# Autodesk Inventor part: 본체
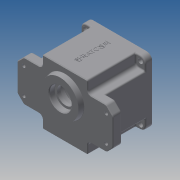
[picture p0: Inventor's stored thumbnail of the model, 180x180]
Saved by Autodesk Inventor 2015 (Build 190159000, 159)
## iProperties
Created: 2016-02
Part Number: 본체
Material: Generic
Document SubType Name: Modeling
Designer: Administrator
Density: 1 g/cm^3
Appearance: Default
Author: Administrator
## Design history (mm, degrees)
sketch "Sketch1"
  geometry: L1 (-70, -20)-(-70, 20); L2 (-33, 47)-(33, 47); L3 (70, 20)-(70, -20); L4 (70, -47)-(-70, 47); L5 (-70, -47)-(70, 47); L6 (60, 30)-(33, 30); L7 (33, 30)-(33, 47); L8 (0, 0)-(114.334, 0); L9 (0, 0)-(0, 123.01); L10 (-33, 30)-(-33, 47); L11 (-60, 30)-(-33, 30); L12 (60, -30)-(33, -30); L13 (33, -30)-(33, -47); L14 (0, 0)-(0, -123.01); L15 (-33, -47)-(33, -47); L16 (-33, -30)-(-33, -47); L17 (-60, -30)-(-33, -30); L18 (70, 20)-(60, 30); L19 (-60, 30)-(-70, 20); L20 (-70, -20)-(-60, -30); L21 (60, -30)-(70, -20); 4 further points
  constraints: 42 end point, 10 symmetric about line, 8 point on line, 2 horizontal, 2 midpoint, 1 parallel, 1 perpendicular, 1 vertical
  dimensions: "d0" = 140 distance of L4.end L5.end; "d1" = 94 distance of L5.start L4.end; "d2" = 66 distance from line of L10 L2.end; "d3" = 60 distance of point (-70, -30) point (-70, 30); "d4" = 94 distance between parallel lines of L15 L2; "d5" = 140 distance between parallel lines of L1 L3; "d6" = 10 distance of L3.start point (70, 30); "d7" = 10 distance of L6.start point (70, 30) (= d6); "d8" = 10 distance of L11.start point (-70, 30); "d9" = 10 distance of L1.end point (-70, 30) (= d8); "d10" = 10 distance of L1.start point (-70, -30) (= d8); "d11" = 10 distance of L17.start point (-70, -30) (= d10); "d12" = 10 distance of L12.start point (70, -30) (= d8); "d13" = 10 distance of L3.end point (70, -30) (= d12)
extrude "Extrusion1" new body sketch "Sketch1" distance "d14" = 13; taper "d15" = 0 deg
sketch "Sketch4"
  geometry: L1 (60, -19)-(-60, -19); L2 (-60, -19)-(-60, 19); L3 (-60, 19)-(60, 19); L4 (60, 19)-(60, -19); L5 (60, -19)-(-60, 19); L6 (-60, -19)-(60, 19); 5 further points
  constraints: 12 end point, 4 coincident, 2 midpoint, 2 parallel, 1 horizontal, 1 perpendicular
  dimensions: "d16" = 120 distance of L2.end L3.end; "d17" = 38 distance of L1.end L2.end
hole "Hole1" sketch "Sketch4" at (-60, 19), (-60, -19), (60, -19), (60, 19) diameter "d18" = 5; stored, may be unused: countersink angle "d22" = 90 deg, drill point angle "d24" = 118 deg; dims "d19" = 6, "d20" = 9, "d21" = 4, "d23" = 8
fillet "Fillet1" dims "d25" = 5
sketch "Sketch5"
  geometry: L1 (-33, -47)-(33, -47) reference; L2 (33, 47)-(-33, 47) reference; L3 (33, 35)-(33, 47) reference; L4 (-33, 47)-(-33, 35) reference; L5 (-33, -35)-(-33, -47) reference; L6 (33, -47)-(33, -35) reference; L7 (47, -30)-(47, 30); L8 (-47, -30)-(-47, 30); L9 (-60, -30)-(-38, -30) reference; L10 (38, -30)-(60, -30) reference; L11 (60, 30)-(38, 30) reference; L12 (-38, 30)-(-60, 30) reference; A1 r 5 centre (38, 35) between (33, 35) and (38, 30) reference; A2 r 5 centre (-38, 35) between (-38, 30) and (-33, 35) reference; A3 r 5 centre (-38, -35) between (-33, -35) and (-38, -30) reference; A4 r 5 centre (38, -35) between (38, -30) and (33, -35) reference; 1 further point
  constraints: 4 end point, 4 point on line, 2 vertical
  dimensions: "d26" = 47 distance from line of point (0, 0) L7; "d27" = 94 distance between parallel lines of L8 L7
extrude "Extrusion2" join sketch "Sketch5" distance "d28" = 57; taper "d29" = 0 deg
sketch "Sketch6"
  geometry: L1 (33, -47)-(-33, -47) reference; L2 (47, 30)-(47, -30) reference; L3 (-47, -30)-(-47, 30) reference; L4 (-33, 47)-(33, 47) reference; L5 (47, -30)-(47, -39); L6 (33, -47)-(39, -47); L7 (-33, -47)-(-39, -47); L8 (-47, -30)-(-47, -39); L9 (47, 30)-(47, 39); L10 (33, 47)-(39, 47); L11 (-33, 47)-(-39, 47); L12 (-47, 30)-(-47, 39); A1 r 8 centre (39, -39) between (39, -47) and (47, -39); A2 r 8 centre (-39, -39) between (-47, -39) and (-39, -47); A3 r 8 centre (-39, 39) between (-39, 47) and (-47, 39); A4 r 8 centre (39, 39) between (47, 39) and (39, 47); 1 further point
  constraints: 16 end point, 8 point on circle, 8 tangent, 4 centre point, 4 vertical, 3 equal radius, 3 horizontal, 1 perpendicular
  dimensions: "d30" = 8 radius of A1
extrude "Extrusion3" join sketch "Sketch6" distance "d31" = 10; taper "d32" = 0 deg
sketch "Sketch7"
  geometry: L1 (40, 40)-(-40, 40); L2 (-40, 40)-(-40, -40); L3 (-40, -40)-(40, -40); L4 (40, -40)-(40, 40); L5 (40, 40)-(-40, -40); L6 (-40, 40)-(40, -40); 5 further points
  constraints: 12 end point, 4 coincident, 2 midpoint, 2 parallel, 1 horizontal, 1 perpendicular
  dimensions: "d33" = 80 distance of L3.end L2.end; "d34" = 80 distance of L2.end L1.end
hole "Hole2" sketch "Sketch7" at (40, -40), (-40, -40), (-40, 40), (40, 40) diameter "d35" = 7; stored, may be unused: countersink angle "d39" = 90 deg, drill point angle "d41" = 118 deg; dims "d36" = 6, "d37" = 9, "d38" = 4, "d40" = 8
sketch "Sketch8"
  geometry: C1 r 43 at (0, 0); 1 further point
  constraints: 1 centre point, 1 coincident
  dimensions: "d42" = 86 diameter of C1
extrude "Extrusion4" cut sketch "Sketch8" distance "d43" = 9; taper "d44" = 0 deg
sketch "Sketch9"
  geometry: L1 (-39, -47)-(39, -47) reference; L2 (47, -39)-(47, 39) reference; L3 (39, 47)-(-39, 47) reference; L4 (-47, 39)-(-47, -39) reference; L5 (-35.777, -4)-(-39.799, -4); L6 (-35.777, 4)-(-39.799, 4); L7 (-42.814, 4)-(-54.27, 4); L8 (39.799, 4)-(35.777, 4); L9 (39.799, -4)-(35.777, -4); C1 r 3.5 at (-40, 40) reference; C2 r 3.5 at (40, -40) reference; C3 r 3.5 at (-40, -40) reference; C4 r 3.5 at (40, 40) reference; A1 r 8 centre (39, -39) between (39, -47) and (47, -39) reference; A2 r 8 centre (39, 39) between (47, 39) and (39, 47) reference; A3 r 8 centre (-39, 39) between (-39, 47) and (-47, 39) reference; A4 r 8 centre (-39, -39) between (-47, -39) and (-39, -47) reference; A5 r 36 centre (0, 0) between (36, 0) and (-36, 0); A6 r 4 centre (36, 0) between (36, 4) and (36, -4); A7 r 4 centre (-36, 0) between (-36, -4) and (-36, 4); A8 r 40 centre (0, 0) between (-39.799, -4) and (39.799, -4); A9 r 40 centre (0, 0) between (39.799, 4) and (-39.799, 4); 2 further points
  constraints: 14 point on circle, 10 end point, 5 centre point, 5 tangent, 4 coincident, 4 point on line, 3 perpendicular, 2 horizontal, 2 horizontal alignment, 1 equal radius, 2 other
  dimensions: "d45" = 36 radius of A5; "d46" = 4 radius of A6; "d49" = 40 radius of A8; "d50" = 40 radius of A9
extrude "Extrusion5" cut sketch "Sketch9" distance "d51" = 62; taper "d52" = 0 deg
sketch "Sketch10"
  geometry: A1 r 21 centre (0, -11) between (-12.163, 6.119) and (12.163, 6.119); A2 r 15 centre (0, 20) between (11.584, 10.47) and (-11.584, 10.47); A3 r 3 centre (13.901, 8.565) between (11.584, 10.47) and (12.163, 6.119); A4 r 3 centre (-13.901, 8.565) between (-12.163, 6.119) and (-11.584, 10.47); 1 further point
  constraints: 8 point on circle, 4 centre point, 4 tangent, 2 vertical alignment, 1 equal radius
  dimensions: "d53" = 11 distance of A1.centre point (0, 0); "d55" = 42 diameter of A1; "d56" = 15 radius of A2; "d57" = 20 distance of A2.centre point (0, 0); "d58" = 3 radius of A3
extrude "Extrusion6" join sketch "Sketch10" distance "d59" = 7; taper "d60" = 0 deg
hole "Hole3" diameter "d63" = 35; stored, may be unused: countersink angle "d67" = 90 deg, drill point angle "d69" = 0 deg; dims "d61" = 10, "d62" = 10, "d64" = 6, "d65" = 9, "d66" = 4, "d68" = 10
hole "Hole4" diameter "d72" = 19; stored, may be unused: countersink angle "d76" = 90 deg, drill point angle "d78" = 0 deg; dims "d70" = 10, "d71" = 10, "d73" = 6, "d74" = 22, "d75" = 7, "d77" = 8
sketch "Sketch11"
  geometry: C1 r 9.5 at (0, -20) reference; C2 r 28 at (0, 11); A1 r 21 centre (0, 11) between (12.163, -6.119) and (-12.163, -6.119) reference; 1 further point
  constraints: 1 centre point, 1 coincident
  dimensions: "d79" = 56 diameter of C2
extrude "Extrusion7" join sketch "Sketch11" distance "d80" = 7; taper "d81" = -10 deg
hole "Hole5" diameter "d84" = 25; stored, may be unused: countersink angle "d88" = 90 deg, drill point angle "d90" = 0 deg; dims "d82" = 10, "d83" = 10, "d85" = 6, "d86" = 32, "d87" = 8, "d89" = 8
sketch "Sketch12"
  geometry: L1 (66, 0)-(0, 0) reference; L2 (-6, 80)-(72, 80) reference; 3 further points
  constraints: 1 midpoint, 1 vertical alignment, 1 other
  dimensions: "d91" = 40 vertical distance of L2.end point (33, 40)
emboss "Emboss1" sketch "Sketch12" dims "d2" = 66, "d3" = 60, "d4" = 94, "d5" = 140, "d6" = 10, "d7" = 10 (= d6), "d8" = 10, "d9" = 10 (= d8), "d10" = 10 (= d8), "d11" = 10 (= d10), "d12" = 10 (= d8), "d13" = 10 (= d12), "d92" = 0.5, "d93" = 0
fillet "Fillet2" dims "d94" = 2
fillet "Fillet3" dims "d95" = 2
fillet "Fillet6" dims "d98" = 2
fillet "Fillet7" dims "d99" = 0.3
fillet "Fillet8" dims "d100" = 0.3
fillet "Fillet9" dims "d101" = 1
chamfer "Chamfer1" distance "d102" = 1; stored, may be unused: second distance "d103" = 2, angle "d104" = 45 deg
hole "Hole6" diameter "d109" = 3.242; stored, may be unused: countersink angle "d113" = 90 deg, drill point angle "d115" = 118 deg; dims "d107" = 10, "d108" = 10, "d110" = 7, "d111" = 4, "d112" = 2, "d114" = 9
hole "Hole7" diameter "d118" = 3.242; stored, may be unused: countersink angle "d122" = 90 deg, drill point angle "d124" = 118 deg; dims "d116" = 10, "d117" = 10, "d119" = 7, "d120" = 4, "d121" = 2, "d123" = 9
fillet "Fillet12" dims "d125" = 5
chamfer "Chamfer2" distance "d126" = 1; stored, may be unused: second distance "d127" = 2, angle "d128" = 45 deg
chamfer "Chamfer3" distance "d129" = 1; stored, may be unused: second distance "d130" = 2, angle "d131" = 45 deg
fillet "Fillet13" dims "d132" = 3.5
fillet "Fillet15" dims "d134" = 2
fillet "Fillet16" dims "d135" = 0.3
fillet "Fillet17" dims "d136" = 2
body "Solid1"
node "Projected Loop1"
